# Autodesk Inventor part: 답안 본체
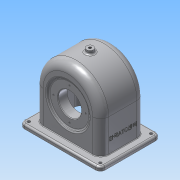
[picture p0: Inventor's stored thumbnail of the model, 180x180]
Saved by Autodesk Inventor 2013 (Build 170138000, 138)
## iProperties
Created: 2016-01
Part Number: 답안 본체
Material: 알루미늄 6061
Document SubType Name: Modeling
Designer: Administrator
Density: 2.71 g/cm^3
Mass: 809.783 g
Surface Area: 999.26 cm^2
Volume: 298.813 cm^3
Author: Administrator
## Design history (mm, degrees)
sketch "스케치1"
  geometry: L1 (-62, 52)-(62, 52); L2 (70, 44)-(70, -44); L3 (62, -52)-(-62, -52); L4 (-70, -44)-(-70, 44); A1 r 8 centre (-62, 44) between (-62, 52) and (-70, 44); A2 r 8 centre (-62, -44) between (-70, -44) and (-62, -52); A3 r 8 centre (62, -44) between (62, -52) and (70, -44); A4 r 8 centre (62, 44) between (70, 44) and (62, 52); 6 further points
  constraints: 8 end point, 8 point on circle, 8 tangent, 6 point on line, 4 centre point, 3 equal radius, 2 midpoint, 2 parallel, 1 horizontal, 1 horizontal alignment, 1 perpendicular, 1 vertical alignment
  dimensions: "d0" = 140 distance of point (-70, 52) point (70, 52); "d2" = 104 distance of point (70, 52) point (70, -52); "d3" = 8 radius of A1
extrude "돌출1" new body sketch "스케치1" distance "d4" = 7; taper "d5" = 0 deg
sketch "스케치2"
  geometry: L1 (62, 7)-(-62, 7) reference; L2 (-57, 7)-(-57, 64); L3 (57, 7)-(57, 64); L4 (-70, 0)-(-70, 7) reference; L5 (-62, 0)-(62, 0) reference; A1 r 57 centre (0, 64) between (57, 64) and (-57, 64); 2 further points
  constraints: 4 end point, 3 point on circle, 2 point on line, 1 centre point, 1 horizontal alignment, 1 parallel, 1 perpendicular, 1 tangent, 1 vertical alignment
  dimensions: "d10" = 57 radius of A1; "d11" = 64 distance from line of L5 L2.end
extrude "돌출2" join sketch "스케치2" stored distance "d12" = 77; taper "d13" = 0 deg
sketch "스케치3"
  geometry: L1 (62, 0)-(-62, 0) reference; C1 r 31 at (0, -60); 1 further point
  constraints: 1 centre point, 1 vertical alignment
  dimensions: "d14" = 62 diameter of C1; "d16" = 60 distance from line of L1 C1.centre
extrude "돌출3" join sketch "스케치3" distance "d17" = 10; taper "d18" = 0 deg
node "작업 평면2"
  node "작업 평면1"
sketch "스케치5"
  geometry: C1 r 6 at (0, 0); 1 further point
  constraints: 1 centre point, 1 coincident
  dimensions: "d20" = 12 diameter of C1
extrude "돌출4" join sketch "스케치5" stored distance "d22" = 5; taper "d23" = 0 deg
sketch "스케치6"
  geometry: L1 (-60.75, 28.203)-(-60.75, 48.797); L2 (-60.75, 48.797)-(14.75, 48.797); L3 (14.75, 48.797)-(14.75, 28.203); L4 (14.75, 28.203)-(-60.75, 28.203); L5 (7, 82.5)-(7, -5.5) reference; 5 further points
  constraints: 3 midpoint, 2 horizontal alignment, 1 parallel, 1 vertical alignment, 2 other
  dimensions: "d24" = 30 distance from line of L5 point (-23, 38.5); "d25" = 7.74973 distance between parallel lines of L3 L5; "d26" = 20.59353 distance between parallel lines of L4 L2
feature "엠보싱1" sketch "스케치6" dims "d0" = 140, "d2" = 104, "d3" = 8, "d27" = 0.5, "d28" = 0
sketch "스케치8"
  geometry: L1 (-57, 7)-(-57, 64) reference; L2 (57, 64)-(57, 7) reference; L3 (-51, 0)-(-51, 64); L4 (51, 64)-(51, 0); L5 (-62, 0)-(62, 0) reference; L6 (-51, 0)-(51, 0); A1 r 57 centre (0, 64) between (57, 64) and (-57, 64) reference; A2 r 51 centre (0, 64) between (51, 64) and (-51, 64); 1 further point
  constraints: 6 end point, 2 horizontal alignment, 2 point on circle, 2 point on line, 2 tangent, 1 centre point
  dimensions: "d30" = 6 radial gap between concentric circles of A1 A2
extrude "돌출5" cut sketch "스케치8" stored distance "d31" = 67; taper "d32" = 0 deg
node "작업 평면3"
sketch "스케치9"
  geometry: C1 r 28 at (0, 60); 1 further point
  constraints: 1 centre point, 1 vertical alignment
  dimensions: "d34" = 56 diameter of C1; "d36" = 60 distance of point (0, 0) C1.centre
extrude "돌출6" join sketch "스케치9" distance "d37" = 16; taper "d38" = 40 deg
hole "구멍1" diameter "d41" = 40; stored, may be unused: countersink angle "d45" = 90 deg, drill point angle "d47" = 0 deg; dims "d42" = 6, "d43" = 4, "d44" = 2, "d46" = 20, "d48" = 10, "d49" = 10
sketch "스케치11"
  geometry: C1 r 31 at (0, 0) reference; A1 r 24 centre (0, 0) between (0, 24) and (-24, 0); 3 further points
  constraints: 4 point on circle, 2 horizontal alignment, 2 vertical alignment, 1 centre point, 1 coincident
  dimensions: "d50" = 48 diameter of A1
hole "구멍2" sketch "스케치11" at (0, 24), (-24, 0), (24, 0), (0, -24) diameter "d52" = 2.459; stored, may be unused: countersink angle "d56" = 90 deg, drill point angle "d58" = 118 deg; dims "d53" = 6, "d54" = 4, "d55" = 2, "d57" = 8
sketch "스케치12"
  geometry: L1 (-19.5, 88)-(-33.5, 99.747) reference; L2 (-19.5, 32)-(-19.5, 88) reference; L3 (-35.5, 60)-(-38.5, 60); L4 (-38.5, 97.416)-(-35.5, 94.899); L5 (-38.5, 121)-(-38.5, 64) reference; L6 (-38.5, 97.416)-(-38.5, 60); L7 (-35.5, 94.899)-(-35.5, 60); 3 further points
  constraints: 8 end point, 3 perpendicular, 2 midpoint, 1 horizontal alignment, 1 point on line
  dimensions: "d59" = 5 distance between parallel lines of L1 L4; "d60" = 3 distance between parallel lines of L7 L6
revolve "회전1" sketch "스케치12" stored, may be unused: angle "d61" = 90 deg
sketch "스케치13"
  geometry: A1 r 28 centre (0, 0) between (0, 28) and (-28, 0); 3 further points
  constraints: 4 point on circle, 3 vertical alignment, 2 horizontal alignment, 1 centre point
  dimensions: "d62" = 56 diameter of A1; "d64" = 60 distance of point (0, -60) A1.centre
hole "구멍3" sketch "스케치13" at (0, 28), (-28, 0), (28, 0), (0, -28) diameter "d65" = 2.459; stored, may be unused: countersink angle "d69" = 90 deg, drill point angle "d71" = 118 deg; dims "d66" = 7, "d67" = 4, "d68" = 2, "d70" = 9
hole "구멍4" diameter "d74" = 40; stored, may be unused: countersink angle "d78" = 90 deg, drill point angle "d80" = 0 deg; dims "d72" = 10, "d73" = 10, "d75" = 7, "d76" = 4, "d77" = 2, "d79" = 16
sketch "스케치14"
  geometry: 5 further points
  constraints: 2 horizontal alignment, 2 vertical alignment
  dimensions: "d81" = 62 horizontal distance of point (0, 0) point (-62, 44); "d82" = 62 horizontal distance of point (62, 44) point (0, 0); "d83" = 44 vertical distance of point (0, 0) point (-62, 44); "d84" = 44 vertical distance of point (-62, -44) point (0, 0)
hole "구멍5" sketch "스케치14" at (-62, 44), (-62, -44), (62, 44), (62, -44) diameter "d85" = 5; stored, may be unused: countersink angle "d89" = 90 deg, drill point angle "d91" = 0 deg; dims "d86" = 7, "d87" = 4, "d88" = 2, "d90" = 7
hole "구멍6" diameter "d94" = 4.459; stored, may be unused: countersink angle "d98" = 90 deg, drill point angle "d100" = 0 deg; dims "d92" = 10, "d93" = 10, "d95" = 7, "d96" = 4, "d97" = 2, "d99" = 7
fillet "모깎기2" dims "d103" = 14
fillet "모깎기3" dims "d104" = 9
fillet "모깎기4" dims "d105" = 1
fillet "모깎기5" dims "d106" = 3
fillet "모깎기6" dims "d107" = 3
chamfer "모따기1" distance "d108" = 1; stored, may be unused: second distance "d109" = 2, angle "d110" = 45 deg
node "솔리드1"
other parameters: "d19" = 6, "d33" = -19
